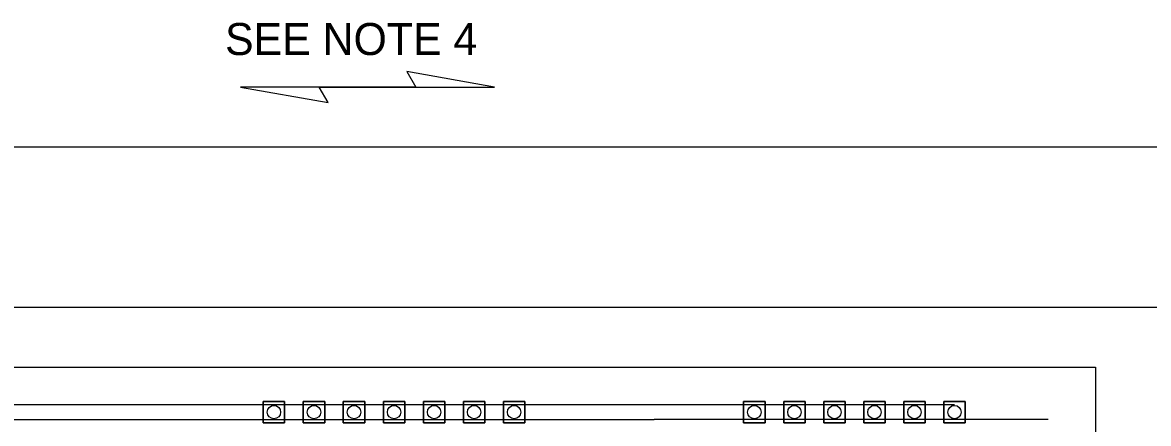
# Model space of a CAD drawing. Extents: x 99999.1 to 100095.7, y 99995 to 100010.7.
# Drawn here: x 100046.43 to 100049.243, y 100005.441 to 100006.443 of the extents above; entities that cross this region are included whole.
import ezdxf

# ---------------------------------------------------------------- set-up
doc = ezdxf.new("R2010")
doc.units = 0
for name, color, linetype in [('RD_ED_ShoulderPavedEdge', 7, 'Continuous'), ('RD_MK_LineDblYellowCenter', 7, 'Continuous'), ('RD_MK_LineEdgeWhite', 7, 'Continuous'), ('RD_MK_LineNoPass', 7, 'Continuous'), ('RD_MK_LineSkipCenter', 7, 'Continuous'), ('TR_WZ_TrafficCone', 7, 'Continuous'), ('TR_WZ_WorkZoneDetails', 7, 'Continuous'), ('TR_WZ_WorkZoneTextCurrent', 7, 'Continuous')]:
    doc.layers.add(name, color=color, linetype=linetype)

msp = doc.modelspace()

# ---------------------------------------------------------------- linework, layer by layer
at = {"layer": 'RD_ED_ShoulderPavedEdge'}
msp.add_line((100040.1076, 100005.7323), (100055.6424, 100005.7323), dxfattribs=at)
at = {"layer": 'RD_MK_LineDblYellowCenter'}
for p, q in [((100045.2015, 100005.4886), (100048.0081, 100005.4886)), ((100045.2015, 100005.4511), (100048.0081, 100005.4511))]:
    msp.add_line(p, q, dxfattribs=at)
at = {"layer": 'RD_MK_LineEdgeWhite'}
msp.add_line((100040.1076, 100006.1323), (100055.6424, 100006.1323), dxfattribs=at)
at = {"layer": 'RD_MK_LineNoPass'}
msp.add_line((100048.0081, 100005.4886), (100048.7581, 100005.4886), dxfattribs=at)
at = {"layer": 'RD_MK_LineSkipCenter'}
msp.add_lwpolyline([(100048.9925, 100005.4511), (100048.0081, 100005.4511)], dxfattribs=at)
at = {"layer": 'TR_WZ_TrafficCone'}
for points in [[(100047.0848, 100005.4965), (100047.0314, 100005.4965), (100047.0314, 100005.4432), (100047.0848, 100005.4432), (100047.0848, 100005.4965)], [(100047.0848, 100005.4432), (100047.0314, 100005.4432), (100047.0314, 100005.4965), (100047.0848, 100005.4965), (100047.0848, 100005.4432)], [(100047.1848, 100005.4965), (100047.1314, 100005.4965), (100047.1314, 100005.4432), (100047.1848, 100005.4432), (100047.1848, 100005.4965)], [(100047.1848, 100005.4432), (100047.1314, 100005.4432), (100047.1314, 100005.4965), (100047.1848, 100005.4965), (100047.1848, 100005.4432)], [(100047.2848, 100005.4965), (100047.2314, 100005.4965), (100047.2314, 100005.4432), (100047.2848, 100005.4432), (100047.2848, 100005.4965)], [(100047.2848, 100005.4432), (100047.2314, 100005.4432), (100047.2314, 100005.4965), (100047.2848, 100005.4965), (100047.2848, 100005.4432)], [(100047.3848, 100005.4965), (100047.3314, 100005.4965), (100047.3314, 100005.4432), (100047.3848, 100005.4432), (100047.3848, 100005.4965)], [(100047.3848, 100005.4432), (100047.3314, 100005.4432), (100047.3314, 100005.4965), (100047.3848, 100005.4965), (100047.3848, 100005.4432)], [(100047.4848, 100005.4965), (100047.4314, 100005.4965), (100047.4314, 100005.4432), (100047.4848, 100005.4432), (100047.4848, 100005.4965)], [(100047.4848, 100005.4432), (100047.4314, 100005.4432), (100047.4314, 100005.4965), (100047.4848, 100005.4965), (100047.4848, 100005.4432)], [(100047.5848, 100005.4965), (100047.5314, 100005.4965), (100047.5314, 100005.4432), (100047.5848, 100005.4432), (100047.5848, 100005.4965)], [(100047.5848, 100005.4432), (100047.5314, 100005.4432), (100047.5314, 100005.4965), (100047.5848, 100005.4965), (100047.5848, 100005.4432)], [(100047.6848, 100005.4965), (100047.6314, 100005.4965), (100047.6314, 100005.4432), (100047.6848, 100005.4432), (100047.6848, 100005.4965)], [(100047.6848, 100005.4432), (100047.6314, 100005.4432), (100047.6314, 100005.4965), (100047.6848, 100005.4965), (100047.6848, 100005.4432)], [(100048.2848, 100005.4965), (100048.2314, 100005.4965), (100048.2314, 100005.4432), (100048.2848, 100005.4432), (100048.2848, 100005.4965)], [(100048.2848, 100005.4432), (100048.2314, 100005.4432), (100048.2314, 100005.4965), (100048.2848, 100005.4965), (100048.2848, 100005.4432)], [(100048.3848, 100005.4965), (100048.3314, 100005.4965), (100048.3314, 100005.4432), (100048.3848, 100005.4432), (100048.3848, 100005.4965)], [(100048.3848, 100005.4432), (100048.3314, 100005.4432), (100048.3314, 100005.4965), (100048.3848, 100005.4965), (100048.3848, 100005.4432)], [(100048.4848, 100005.4965), (100048.4314, 100005.4965), (100048.4314, 100005.4432), (100048.4848, 100005.4432), (100048.4848, 100005.4965)], [(100048.4848, 100005.4432), (100048.4314, 100005.4432), (100048.4314, 100005.4965), (100048.4848, 100005.4965), (100048.4848, 100005.4432)], [(100048.5848, 100005.4965), (100048.5314, 100005.4965), (100048.5314, 100005.4432), (100048.5848, 100005.4432), (100048.5848, 100005.4965)], [(100048.5848, 100005.4432), (100048.5314, 100005.4432), (100048.5314, 100005.4965), (100048.5848, 100005.4965), (100048.5848, 100005.4432)], [(100048.6848, 100005.4965), (100048.6314, 100005.4965), (100048.6314, 100005.4432), (100048.6848, 100005.4432), (100048.6848, 100005.4965)], [(100048.6848, 100005.4432), (100048.6314, 100005.4432), (100048.6314, 100005.4965), (100048.6848, 100005.4965), (100048.6848, 100005.4432)], [(100048.7848, 100005.4965), (100048.7314, 100005.4965), (100048.7314, 100005.4432), (100048.7848, 100005.4432), (100048.7848, 100005.4965)], [(100048.7848, 100005.4432), (100048.7314, 100005.4432), (100048.7314, 100005.4965), (100048.7848, 100005.4965), (100048.7848, 100005.4432)]]:
    msp.add_lwpolyline(points, dxfattribs=at)
for centre in [(100047.0581, 100005.4698), (100047.1581, 100005.4698), (100047.2581, 100005.4698), (100047.3581, 100005.4698), (100047.4581, 100005.4698), (100047.5581, 100005.4698), (100047.6581, 100005.4698), (100048.2581, 100005.4698), (100048.3581, 100005.4698), (100048.4581, 100005.4698), (100048.5581, 100005.4698), (100048.6581, 100005.4698), (100048.7581, 100005.4698)]:
    msp.add_circle(centre, 0.0167, dxfattribs=at)
at = {"layer": 'TR_WZ_WorkZoneDetails'}
for p, q in [((100047.1713, 100006.2816), (100047.4124, 100006.2816)), ((100047.4124, 100006.2816), (100047.1713, 100006.2816))]:
    msp.add_line(p, q, dxfattribs=at)
for points in [[(100047.609, 100006.2816), (100047.3901, 100006.3202), (100047.4124, 100006.2816)], [(100046.9748, 100006.2816), (100047.1936, 100006.243), (100047.1713, 100006.2816)]]:
    msp.add_lwpolyline(points, close=True, dxfattribs=at)
at = {"layer": 'TR_WZ_WorkZoneTextCurrent'}
msp.add_lwpolyline([(100045.1015, 100005.5823), (100049.1102, 100005.5823), (100049.1102, 100003.4799), (100045.1015, 100003.4799)], close=True, dxfattribs=at)

# ---------------------------------------------------------------- texts
msp.add_text('SEE NOTE 4', height=0.08, dxfattribs=at).set_placement((100046.9359, 100006.3616))

doc.saveas('drawing.dxf')
